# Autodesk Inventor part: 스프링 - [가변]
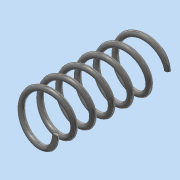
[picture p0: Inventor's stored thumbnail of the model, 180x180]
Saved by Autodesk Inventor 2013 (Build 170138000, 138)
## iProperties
Created: 2016-04
Part Number: 스프링 - [가변]
Material: 강철, 탄소
Document SubType Name: Modeling
Designer: dgall
Density: 7.87 g/cm^3
Mass: 7.38132 g
Surface Area: 18.9918 cm^2
Volume: 0.937905 cm^3
Author: dgall
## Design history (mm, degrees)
sketch "스케치1"
  geometry: L1 (0, 0)-(0, 42); L2 (0, 0)-(8, 0); L3 (0, 42)-(14.42, 42); C1 r 1 at (8, 0)
  constraints: 6 end point, 1 centre point, 1 coincident, 1 parallel, 1 perpendicular, 1 vertical
  dimensions: "d0" = 41.99997 distance of L1.start L1.end (derived); "d1" = 16 diameter of L2.end L1; "d2" = 2 diameter of C1
feature "코일1" pitch "d3" = 10; turns "d5" = 6; dims "d4" = 41.99997 (= d0), "d6" = 0, angle "d7" = 90 deg, angle "d8" = 90 deg, "d9" = 0, "d10" = 0
feature "분할1"
node "작업 평면1"
feature "분할2"
node "솔리드1"
other parameters: "d11" = 0
